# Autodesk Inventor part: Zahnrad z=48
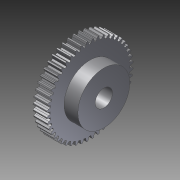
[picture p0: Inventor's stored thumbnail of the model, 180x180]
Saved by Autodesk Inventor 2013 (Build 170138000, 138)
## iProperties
Created: 2012-07
Part Number: Zahnrad z=48
Material: Stahl
Document SubType Name: Modeling
Designer: rYan
Mass: 18.3991 g
Surface Area: 17.4108 cm^2
Volume: 2.34384 cm^3
Density: 7.85 g/cm^3
Übersetzungsnorm: STEP AP214IS
Dateiname: c:/PPEXPORT/antriebselemente_und_normteile/stirnzahnraeder/stirnzahnraeder_stahl/modul_05_und_07/artikel_nr___21104800.stp
Postprozessor: Build: 138, Release: 2013 RTM - Date: Thu 03/01/2012
Gesendete Einheiten: Millimeter
Unbestimmtheit: 1.0000000000000002e-06
Author: rYan
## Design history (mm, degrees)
node "11"
node "1"
node "Basis1"
